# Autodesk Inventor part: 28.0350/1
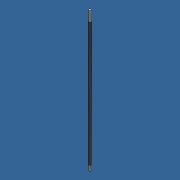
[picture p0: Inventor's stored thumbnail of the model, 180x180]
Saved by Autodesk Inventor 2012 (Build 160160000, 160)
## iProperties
Created: 2011-09
Part Number: 28.0350/1
Document SubType Name: Modeling
Designer: Administrator
Density: 8.08 g/cm^3
Description: MACHINE TO PRINT 28.0350/1
Stock Number: 28.0364 M8X1.25 LEADSCREW
Material: Stainless Steel
Mass: 158.33 g
Surface Area: 101.337 cm^2
Volume: 19.5953 cm^3
Vendor: F
Author: Administrator
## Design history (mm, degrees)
sketch "Sketch1"
  geometry: C1 r 3 at (0, 0); 1 further point
  constraints: 1 centre point, 1 coincident
  dimensions: "d0" = 6 diameter of C1
extrude "Extrusion1" new body sketch "Sketch1" distance "d1" = 31.1; taper "d2" = 0 deg
sketch "Sketch2"
  geometry: L1 (-2.236, 2)-(2.236, 2); A1 r 3 centre (0, 0) between (-2.236, 2) and (2.236, 2) reference
  constraints: 2 end point, 2 point on circle, 1 horizontal
  dimensions: "d3" = 5 dimension on A1 L1
extrude "Extrusion2" cut sketch "Sketch2" distance "d4" = 9; taper "d5" = 0 deg
sketch "Sketch3"
  geometry: L1 (4.472, 0)-(0, 0) reference; 3 further points
  constraints: 1 midpoint, 1 vertical alignment
  dimensions: "d6" = 5.5 distance from line of point (2.236, 5.5) L1
hole "Hole1" sketch "Sketch3" at (2.236, 5.5) diameter "d7" = 4; stored, may be unused: countersink angle "d11" = 90 deg, drill point angle "d13" = 118 deg; dims "d8" = 6, "d9" = 4, "d10" = 2, "d12" = 0.01
sketch "Sketch4"
  geometry: C1 r 3 at (0, 0) reference; C2 r 4 at (0, 0)
  constraints: 1 centre point, 1 coincident
  dimensions: "d14" = 8 diameter of C2
extrude "Extrusion3" join sketch "Sketch4" distance "d15" = 364 (computed from TRAVEL); taper "d16" = 0 deg
thread "Thread1" dims "d17" = 10, "d18" = 0
sketch "Sketch5"
  geometry: C1 r 4 at (0, 0) reference; C2 r 3 at (0, 0)
  constraints: 1 centre point, 1 coincident
  dimensions: "d19" = 6 diameter of C2
extrude "Extrusion4" join sketch "Sketch5" distance "d20" = 16; taper "d21" = 0 deg
body "Solid1"
other parameters: "TRAVEL" = 305 [user parameter; used in 1 equation term]
